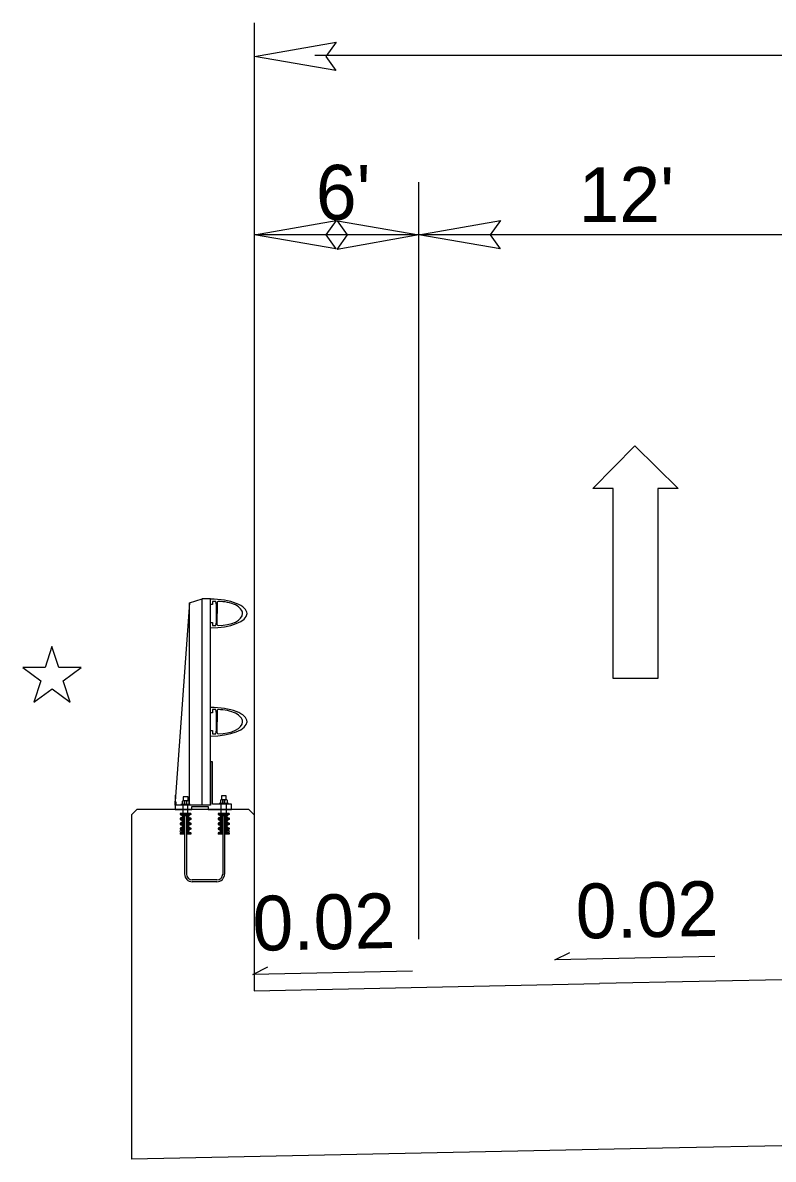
# Model space of a CAD drawing. Extents: x 573813 to 575363, y -54752 to -53123.
# Drawn here: x 574334.93 to 574362.34, y -54173.49 to -54132.02 of the extents above; entities that cross this region are included whole.
import ezdxf

# ---------------------------------------------------------------- set-up
doc = ezdxf.new("R2010")
doc.units = 0
for name, color, linetype in [('Old_Level_1', 7, 'Continuous'), ('Old_Level_11', 7, 'Continuous'), ('Old_Level_4', 7, 'Continuous'), ('Prop RDY Traffic Signal CELL', 7, 'Continuous'), ('Typical Bridge Rail Two Bar CELL', 7, 'Continuous')]:
    doc.layers.add(name, color=color, linetype=linetype)

msp = doc.modelspace()

# ---------------------------------------------------------------- linework, layer by layer
at = {"layer": 'Old_Level_1'}
for p, q in [((574354.363, -54166.218), (574354.913, -54165.943)), ((574360.201, -54166.097), (574354.363, -54166.218)), ((574343.333, -54166.748), (574343.884, -54166.473)), ((574349.172, -54166.626), (574343.333, -54166.748)), ((574365.899, -54166.877), (574356, -54167.083)), ((574343.382, -54167.345), (574356, -54167.083)), ((574378.06, -54172.681), (574358.294, -54173.092)), ((574358.294, -54173.09), (574338.91, -54173.493))]:
    msp.add_line(p, q, dxfattribs=at)
at = {"layer": 'Old_Level_11'}
for p, q in [((574343.398, -54165.492), (574343.399, -54132.018)), ((574410.403, -54133.212), (574345.602, -54133.212)), ((574349.399, -54165.459), (574349.399, -54137.838)), ((574349.399, -54139.761), (574343.398, -54139.761)), ((574365.899, -54139.761), (574349.399, -54139.761))]:
    msp.add_line(p, q, dxfattribs=at)
for points in [[(574346.369, -54133.767), (574343.399, -54133.256), (574346.385, -54132.728), (574346.006, -54133.256)], [(574346.368, -54140.272), (574343.398, -54139.761), (574346.385, -54139.233), (574346.006, -54139.761)], [(574346.429, -54139.249), (574349.399, -54139.761), (574346.412, -54140.289), (574346.791, -54139.761)], [(574352.368, -54140.272), (574349.399, -54139.761), (574352.385, -54139.233), (574352.006, -54139.761)]]:
    msp.add_lwpolyline(points, close=True, dxfattribs=at)
at = {"layer": 'Old_Level_4'}
for p, q in [((574355.75, -54149.018), (574357.284, -54147.459)), ((574357.284, -54147.459), (574358.868, -54149.018)), ((574356.492, -54149.018), (574355.75, -54149.018)), ((574356.492, -54155.948), (574356.492, -54149.018)), ((574358.868, -54149.018), (574358.126, -54149.018)), ((574358.126, -54149.018), (574358.126, -54155.948)), ((574358.126, -54155.948), (574356.492, -54155.948))]:
    msp.add_line(p, q, dxfattribs=at)
at = {"layer": 'Prop RDY Traffic Signal CELL'}
msp.add_lwpolyline([(574335.751, -54155.553), (574334.935, -54155.553), (574335.595, -54156.032), (574335.342, -54156.81), (574336.004, -54156.329), (574336.665, -54156.809), (574336.412, -54156.032), (574337.073, -54155.552), (574336.256, -54155.552), (574336.003, -54154.775), (574335.751, -54155.553)], dxfattribs=at)
at = {"layer": 'Typical Bridge Rail Two Bar CELL'}
for p, q in [((574341.03, -54153.191), (574340.505, -54160.427)), ((574341.03, -54153.191), (574341.486, -54153.043)), ((574341.03, -54160.577), (574341.03, -54153.191)), ((574341.787, -54153.043), (574341.486, -54153.043)), ((574341.486, -54160.577), (574341.486, -54153.043)), ((574341.787, -54160.577), (574341.787, -54153.043)), ((574342.039, -54153.167), (574342.039, -54153.577)), ((574342.039, -54153.986), (574342.039, -54153.577)), ((574341.03, -54156.648), (574341.014, -54156.648)), ((574342.039, -54157.117), (574342.039, -54157.525)), ((574342.039, -54157.935), (574342.039, -54157.525)), ((574340.519, -54160.342), (574340.519, -54160.21)), ((574340.97, -54160.273), (574340.798, -54160.273)), ((574340.798, -54160.273), (574340.798, -54160.414)), ((574340.97, -54160.414), (574340.97, -54160.273)), ((574342.366, -54160.233), (574342.193, -54160.233)), ((574342.193, -54160.233), (574342.193, -54160.375)), ((574342.366, -54160.375), (574342.366, -54160.233)), ((574338.91, -54160.923), (574339.105, -54160.728)), ((574343.187, -54160.728), (574339.105, -54160.728)), ((574340.505, -54160.577), (574340.505, -54160.427)), ((574340.795, -54160.91), (574340.795, -54160.577)), ((574340.968, -54160.91), (574340.968, -54160.577)), ((574342.184, -54160.873), (574342.184, -54160.539)), ((574342.373, -54160.873), (574342.373, -54160.539)), ((574343.187, -54160.728), (574343.382, -54160.923)), ((574338.91, -54160.923), (574338.91, -54173.493)), ((574341.079, -54160.873), (574340.679, -54160.873)), ((574341.079, -54160.917), (574340.679, -54160.917)), ((574340.845, -54161.05), (574340.679, -54161.05)), ((574340.845, -54161.094), (574340.679, -54161.094)), ((574340.845, -54161.228), (574340.679, -54161.228)), ((574340.845, -54160.962), (574340.767, -54160.962)), ((574340.845, -54161.006), (574340.767, -54161.006)), ((574340.845, -54161.14), (574340.767, -54161.14)), ((574340.845, -54161.184), (574340.767, -54161.184)), ((574340.912, -54160.961), (574340.845, -54160.961)), ((574340.845, -54160.961), (574340.845, -54163.084)), ((574340.912, -54160.961), (574340.912, -54163.084)), ((574340.99, -54160.962), (574340.912, -54160.962)), ((574340.99, -54161.006), (574340.912, -54161.006)), ((574341.079, -54161.05), (574340.912, -54161.05)), ((574341.079, -54161.094), (574340.912, -54161.094)), ((574340.99, -54161.14), (574340.912, -54161.14)), ((574340.99, -54161.184), (574340.912, -54161.184)), ((574341.079, -54161.228), (574340.912, -54161.228)), ((574342.473, -54160.873), (574342.072, -54160.873)), ((574342.473, -54160.917), (574342.072, -54160.917)), ((574342.24, -54161.05), (574342.072, -54161.05)), ((574342.24, -54161.094), (574342.072, -54161.094)), ((574342.24, -54161.228), (574342.072, -54161.228)), ((574342.24, -54160.962), (574342.161, -54160.962)), ((574342.24, -54161.006), (574342.161, -54161.006)), ((574342.24, -54161.14), (574342.161, -54161.14)), ((574342.24, -54161.184), (574342.161, -54161.184)), ((574342.24, -54160.961), (574342.24, -54163.084)), ((574342.306, -54160.962), (574342.24, -54160.962)), ((574342.306, -54160.961), (574342.306, -54163.084)), ((574342.384, -54160.962), (574342.306, -54160.962)), ((574342.384, -54161.006), (574342.306, -54161.006)), ((574342.473, -54161.05), (574342.306, -54161.05)), ((574342.473, -54161.094), (574342.306, -54161.094)), ((574342.384, -54161.14), (574342.306, -54161.14)), ((574342.384, -54161.184), (574342.306, -54161.184)), ((574342.473, -54161.228), (574342.306, -54161.228)), ((574343.382, -54160.923), (574343.382, -54167.345)), ((574340.845, -54161.273), (574340.679, -54161.273)), ((574340.845, -54161.405), (574340.679, -54161.405)), ((574340.845, -54161.45), (574340.679, -54161.45)), ((574340.845, -54161.583), (574340.679, -54161.583)), ((574340.845, -54161.627), (574340.679, -54161.627)), ((574340.845, -54161.317), (574340.767, -54161.317)), ((574340.845, -54161.361), (574340.767, -54161.361)), ((574340.845, -54161.495), (574340.767, -54161.495)), ((574340.845, -54161.539), (574340.767, -54161.539)), ((574341.079, -54161.273), (574340.912, -54161.273)), ((574340.99, -54161.317), (574340.912, -54161.317)), ((574340.99, -54161.361), (574340.912, -54161.361)), ((574341.079, -54161.405), (574340.912, -54161.405)), ((574341.079, -54161.45), (574340.912, -54161.45)), ((574340.99, -54161.495), (574340.912, -54161.495)), ((574340.99, -54161.539), (574340.912, -54161.539)), ((574341.079, -54161.583), (574340.912, -54161.583)), ((574341.079, -54161.627), (574340.912, -54161.627)), ((574342.24, -54161.273), (574342.072, -54161.273)), ((574342.24, -54161.405), (574342.072, -54161.405)), ((574342.24, -54161.45), (574342.072, -54161.45)), ((574342.24, -54161.583), (574342.072, -54161.583)), ((574342.24, -54161.627), (574342.072, -54161.627)), ((574342.24, -54161.317), (574342.161, -54161.317)), ((574342.24, -54161.361), (574342.161, -54161.361)), ((574342.24, -54161.495), (574342.161, -54161.495)), ((574342.24, -54161.539), (574342.161, -54161.539)), ((574342.473, -54161.273), (574342.306, -54161.273)), ((574342.384, -54161.317), (574342.306, -54161.317)), ((574342.384, -54161.361), (574342.306, -54161.361)), ((574342.473, -54161.405), (574342.306, -54161.405)), ((574342.473, -54161.45), (574342.306, -54161.45)), ((574342.384, -54161.495), (574342.306, -54161.495)), ((574342.384, -54161.539), (574342.306, -54161.539)), ((574342.473, -54161.583), (574342.306, -54161.583)), ((574342.473, -54161.627), (574342.306, -54161.627)), ((574342.027, -54163.296), (574341.126, -54163.296)), ((574342.027, -54163.363), (574341.126, -54163.363))]:
    msp.add_line(p, q, dxfattribs=at)
for points in [[(574341.787, -54154.098), (574341.787, -54153.903), (574341.868, -54153.903), (574341.868, -54153.936), (574341.86, -54153.936), (574341.86, -54154.018), (574341.99, -54154.018), (574342.007, -54153.892), (574342.007, -54153.577), (574342.007, -54153.262), (574341.99, -54153.136), (574341.86, -54153.136), (574341.86, -54153.218), (574341.868, -54153.218), (574341.868, -54153.251), (574341.787, -54153.251), (574341.787, -54153.054)], [(574341.787, -54158.048), (574341.787, -54157.852), (574341.868, -54157.852), (574341.868, -54157.884), (574341.86, -54157.884), (574341.86, -54157.966), (574341.99, -54157.966), (574342.007, -54157.84), (574342.007, -54157.525), (574342.007, -54157.21), (574341.99, -54157.086), (574341.86, -54157.086), (574341.86, -54157.166), (574341.868, -54157.166), (574341.868, -54157.199), (574341.787, -54157.199), (574341.787, -54157.004)], [(574342.56, -54160.728), (574342.56, -54160.539), (574341.863, -54160.539), (574341.863, -54158.993), (574341.787, -54158.993), (574341.787, -54160.577), (574340.54, -54160.577), (574340.54, -54160.466), (574340.505, -54160.466), (574340.505, -54160.728), (574341.106, -54160.728), (574341.106, -54160.623), (574341.712, -54160.623), (574341.712, -54160.728), (574342.56, -54160.728)], [(574342.406, -54160.507), (574342.406, -54160.398), (574342.386, -54160.376), (574342.173, -54160.376), (574342.151, -54160.398), (574342.151, -54160.507), (574342.406, -54160.507), (574342.32, -54160.507), (574342.32, -54160.398), (574342.343, -54160.376), (574342.32, -54160.398), (574342.3, -54160.376), (574342.256, -54160.376), (574342.236, -54160.398), (574342.236, -54160.507), (574342.236, -54160.398), (574342.216, -54160.376)], [(574341.054, -54160.579), (574341.054, -54160.545), (574340.883, -54160.545), (574340.711, -54160.545), (574340.711, -54160.579)], [(574341.01, -54160.545), (574341.01, -54160.435), (574340.989, -54160.414), (574340.778, -54160.414), (574340.756, -54160.435), (574340.756, -54160.545), (574341.01, -54160.545), (574340.926, -54160.545), (574340.926, -54160.435), (574340.947, -54160.414), (574340.926, -54160.435), (574340.905, -54160.414), (574340.861, -54160.414), (574340.84, -54160.435), (574340.84, -54160.545), (574340.84, -54160.435), (574340.819, -54160.414)], [(574342.454, -54160.54), (574342.454, -54160.506), (574342.281, -54160.506), (574342.109, -54160.506), (574342.109, -54160.54)], [(574340.679, -54160.873), (574340.679, -54160.917), (574340.767, -54160.962), (574340.767, -54161.006), (574340.679, -54161.05), (574340.679, -54161.094), (574340.767, -54161.14), (574340.767, -54161.184), (574340.679, -54161.228), (574340.679, -54161.273), (574340.767, -54161.317), (574340.767, -54161.361), (574340.679, -54161.405), (574340.679, -54161.45), (574340.767, -54161.495), (574340.767, -54161.539), (574340.679, -54161.583), (574340.679, -54161.627)], [(574341.079, -54160.873), (574341.079, -54160.917), (574340.991, -54160.962), (574340.991, -54161.006), (574341.079, -54161.05), (574341.079, -54161.094), (574340.991, -54161.14), (574340.991, -54161.184), (574341.079, -54161.228), (574341.079, -54161.273), (574340.991, -54161.317), (574340.991, -54161.361), (574341.079, -54161.405), (574341.079, -54161.45), (574340.991, -54161.495), (574340.991, -54161.539), (574341.079, -54161.583), (574341.079, -54161.627)], [(574342.072, -54160.873), (574342.072, -54160.917), (574342.161, -54160.962), (574342.161, -54161.006), (574342.072, -54161.05), (574342.072, -54161.094), (574342.161, -54161.14), (574342.161, -54161.184), (574342.072, -54161.228), (574342.072, -54161.273), (574342.161, -54161.317), (574342.161, -54161.361), (574342.072, -54161.405), (574342.072, -54161.45), (574342.161, -54161.495), (574342.161, -54161.539), (574342.072, -54161.583), (574342.072, -54161.627)], [(574342.474, -54160.873), (574342.474, -54160.917), (574342.384, -54160.962), (574342.384, -54161.006), (574342.474, -54161.05), (574342.474, -54161.094), (574342.384, -54161.14), (574342.384, -54161.184), (574342.474, -54161.228), (574342.474, -54161.273), (574342.384, -54161.317), (574342.384, -54161.361), (574342.474, -54161.405), (574342.474, -54161.45), (574342.384, -54161.495), (574342.384, -54161.539), (574342.474, -54161.583), (574342.474, -54161.627)]]:
    msp.add_lwpolyline(points, dxfattribs=at)
for centre in [(574340.714, -54161.517), (574342.439, -54161.517)]:
    msp.add_circle(centre, 0.0334, dxfattribs=at)
for centre, radius, start, end in [((574342.071, -54153.168), 0.0313, 90, 180), ((574342.071, -54153.986), 0.0313, 180, 270), ((574342.071, -54157.116), 0.0313, 90, 180), ((574342.071, -54157.935), 0.0313, 180, 270), ((574341.126, -54163.084), 0.28, 180, 270), ((574341.126, -54163.084), 0.214, 180, 270), ((574342.026, -54163.084), 0.214, 270, 0), ((574342.026, -54163.084), 0.28, 270, 0)]:
    msp.add_arc(centre, radius, start, end, dxfattribs=at)
for centre, major_axis, ratio, start_param, end_param in [((574341.787, -54153.577), (1.338, 0), 0.39036, 6.282787, 7.853967), ((574342.071, -54153.577), (0.889, 0), 0.495501, 6.282718, 7.853881), ((574341.787, -54153.577), (1.338, 0), 0.39036, 4.712404, 6.282787), ((574342.071, -54153.577), (0.889, 0), 0.495501, 4.712489, 6.282718), ((574341.787, -54157.526), (1.338, 0), 0.39036, 6.282787, 7.853967), ((574342.071, -54157.526), (0.889, 0), 0.495501, 6.282718, 7.853881), ((574341.787, -54157.526), (1.338, 0), 0.39036, 4.712404, 6.282787), ((574342.071, -54157.526), (0.889, 0), 0.495501, 4.712489, 6.282718)]:
    msp.add_ellipse(centre, major_axis=major_axis, ratio=ratio, start_param=start_param, end_param=end_param, dxfattribs=at)

# ---------------------------------------------------------------- texts
at = {"layer": 'Old_Level_1'}
for p in [(574355.146, -54165.443), (574343.346, -54165.887)]:
    msp.add_text('0.02', height=2, rotation=1.1918, dxfattribs=at).set_placement(p)
at = {"layer": 'Old_Level_11'}
for s, p in [("6'", (574345.639, -54139.206)), ("12'", (574355.234, -54139.291))]:
    msp.add_text(s, height=2, rotation=359.9999, dxfattribs=at).set_placement(p)

doc.saveas('drawing.dxf')
